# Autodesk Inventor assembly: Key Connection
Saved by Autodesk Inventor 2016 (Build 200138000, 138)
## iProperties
Created: 2015-08
Part Number: Key Connection
Document SubType Name: Assembly
Designer: Ugljesa
ClientObjectVersion: 1
Author: Ugljesa
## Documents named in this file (2)
- C:\Users\Ugljesa\Desktop\Turbokompr\Sklop turbokompresora\Design Accelerator\Key Connection1.iam
- C:\Users\Ugljesa\Documents\Inventor\Content Center Files\R2016\en-US\ISO 2491 - A\ISO 2491 - A  8 x 5 x 18.ipt
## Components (1 placed, 1 different names)
1. ISO 2491 A A  8 x 5 x 18:1
